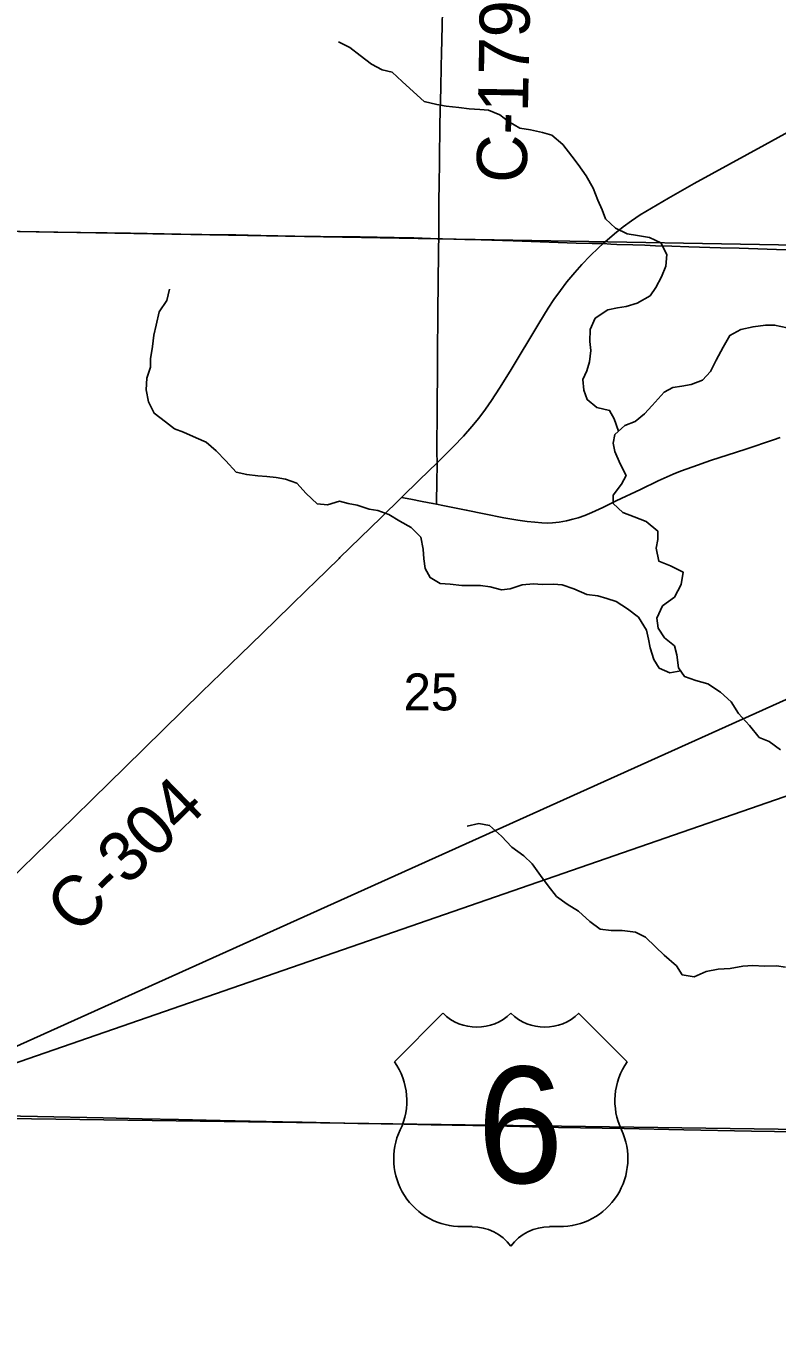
# Model space of a CAD drawing. Extents: x 0 to 34, y 0 to 22.
# Drawn here: x 4.764 to 5.615, y 15.338 to 16.807 of the extents above; entities that cross this region are included whole.
import ezdxf

# ---------------------------------------------------------------- set-up
doc = ezdxf.new("R2010")
doc.units = 0
for name, color, linetype in [('GM_X_Corporation', 7, 'Continuous'), ('GM_X_County_Road', 7, 'Continuous'), ('GM_X_County_Road_Text', 7, 'Continuous'), ('GM_X_Minor_River', 7, 'Continuous'), ('GM_X_Section_Text', 7, 'Continuous'), ('GM_X_State_Route', 7, 'Continuous'), ('GM_X_US_Location', 7, 'Continuous'), ('GM_X_US_Route', 7, 'Continuous'), ('GM_X_US_Shield', 7, 'Continuous'), ('SH_Data', 7, 'Continuous')]:
    doc.layers.add(name, color=color, linetype=linetype)

msp = doc.modelspace()

# ---------------------------------------------------------------- linework, layer by layer
at = {"layer": 'GM_X_Corporation'}
for points in [[(4.7439, 17.5807), (5.7581, 17.5537), (5.7459, 16.557), (4.7141, 16.575)], [(4.7141, 16.575), (5.7459, 16.557), (5.726, 15.5556), (4.7157, 15.5696)], [(4.7157, 15.5696), (5.726, 15.5556), (5.7061, 14.5519), (4.7065, 14.5692)]]:
    msp.add_lwpolyline(points, close=True, dxfattribs=at)
at = {"layer": 'GM_X_County_Road'}
for points in [[(5.232, 16.5662), (5.2321, 16.5737), (5.2321, 16.587), (5.2321, 16.5976), (5.2323, 16.6106), (5.2325, 16.6269), (5.2328, 16.6542), (5.2333, 16.6964), (5.2343, 16.7368), (5.2347, 16.7616), (5.235, 16.7759), (5.2358, 16.8076), (5.2368, 16.8424), (5.2374, 16.8642), (5.2384, 16.8921), (5.2387, 16.9089), (5.2399, 16.9455), (5.2405, 16.9723), (5.2412, 16.9928), (5.2416, 17.0058), (5.242, 17.0181), (5.2425, 17.0353), (5.2434, 17.0647)], [(5.4185, 16.5607), (5.4228, 16.5647), (5.4314, 16.5719), (5.4411, 16.5796), (5.4506, 16.5865), (5.4604, 16.5931), (5.473, 16.601), (5.4923, 16.6122), (5.5216, 16.6286), (5.6017, 16.6726), (5.6436, 16.6958), (5.6963, 16.725), (5.7198, 16.738), (5.7398, 16.7492), (5.7497, 16.7549)], [(4.6889, 16.5753), (4.6917, 16.5753), (4.7557, 16.5744), (4.7957, 16.5737), (4.8564, 16.5728), (4.8826, 16.5725), (4.9397, 16.5714), (4.9634, 16.5711), (5.0019, 16.5705), (5.0305, 16.5699), (5.069, 16.5692), (5.0982, 16.5688), (5.143, 16.5682), (5.1815, 16.5676), (5.2039, 16.5671), (5.232, 16.5662)], [(5.2301, 16.3123), (5.23, 16.3242), (5.23, 16.3422), (5.2301, 16.3571), (5.2303, 16.377), (5.2303, 16.3876), (5.2305, 16.4062), (5.2305, 16.4143), (5.2306, 16.4277), (5.2308, 16.4491), (5.2309, 16.4677), (5.231, 16.4851), (5.2312, 16.515), (5.2314, 16.5261), (5.2316, 16.5417), (5.2319, 16.5567), (5.232, 16.5662)], [(5.232, 16.5662), (5.2362, 16.5662), (5.2616, 16.5654), (5.2803, 16.5649), (5.3163, 16.5638), (5.3878, 16.5613), (5.406, 16.5607), (5.4129, 16.5606), (5.4185, 16.5607)], [(5.2301, 16.3123), (5.2316, 16.3138), (5.2488, 16.3309), (5.26, 16.3426), (5.2695, 16.3534), (5.2774, 16.363), (5.2849, 16.373), (5.2917, 16.3827), (5.3009, 16.3968), (5.313, 16.4163), (5.3453, 16.4702), (5.3561, 16.4876), (5.3626, 16.4974), (5.3699, 16.5075), (5.3774, 16.5173), (5.3861, 16.5278), (5.3944, 16.5371), (5.4038, 16.5469), (5.4132, 16.556), (5.4185, 16.5607)], [(5.4185, 16.5607), (5.4269, 16.5601), (5.434, 16.5598), (5.4521, 16.5591), (5.4657, 16.5587), (5.4777, 16.5583), (5.4962, 16.5578), (5.5156, 16.557), (5.5514, 16.5558), (5.5725, 16.5553), (5.5937, 16.5547), (5.6148, 16.5541), (5.6496, 16.5532), (5.6682, 16.553), (5.6924, 16.5527), (5.7136, 16.5527), (5.7344, 16.5529), (5.7459, 16.5531), (5.7477, 16.5532), (5.7493, 16.5533)], [(5.6191, 16.3408), (5.6114, 16.3383), (5.5801, 16.3279), (5.5695, 16.3244), (5.54, 16.3147), (5.52, 16.3079), (5.506, 16.3027), (5.4979, 16.2994), (5.4809, 16.2917), (5.4607, 16.282), (5.4332, 16.269), (5.4181, 16.2617), (5.4057, 16.256), (5.3977, 16.2527), (5.3901, 16.25), (5.3842, 16.2483), (5.377, 16.2466), (5.3685, 16.2452), (5.3611, 16.2443), (5.3556, 16.244), (5.3489, 16.2443), (5.3409, 16.2449), (5.3322, 16.2457), (5.3218, 16.2472), (5.3059, 16.25), (5.2834, 16.2545), (5.2633, 16.2587), (5.2365, 16.264), (5.2295, 16.2654)], [(5.1899, 16.273), (5.2104, 16.2928), (5.2301, 16.3123)], [(5.2295, 16.2654), (5.2296, 16.2694), (5.2298, 16.2887), (5.2301, 16.3123)], [(4.7186, 15.8132), (4.7288, 15.8231), (4.7596, 15.853), (4.8183, 15.9103), (4.84, 15.9317), (4.8761, 15.9669), (4.9636, 16.0526), (5.0072, 16.0951), (5.0319, 16.1188), (5.0648, 16.1509), (5.0824, 16.1685), (5.0919, 16.1775), (5.119, 16.204), (5.1199, 16.2049), (5.1663, 16.2499), (5.1899, 16.273)], [(5.2295, 16.2654), (5.2255, 16.2662), (5.2133, 16.2685), (5.2005, 16.271), (5.1899, 16.273)]]:
    msp.add_lwpolyline(points, dxfattribs=at)
at = {"layer": 'GM_X_Minor_River'}
for points in [[(5.4359, 16.3482), (5.4308, 16.3622), (5.4257, 16.3717), (5.4114, 16.375), (5.4002, 16.384), (5.3966, 16.3947), (5.3953, 16.4065), (5.4, 16.4166), (5.4029, 16.4268), (5.4043, 16.4397), (5.4033, 16.4499), (5.4036, 16.4632), (5.4095, 16.476), (5.4237, 16.4856), (5.4348, 16.4877), (5.4443, 16.4894), (5.4569, 16.4933), (5.4715, 16.5014), (5.4781, 16.5111), (5.4844, 16.5231), (5.4895, 16.5352), (5.4906, 16.5484), (5.4836, 16.5615), (5.4708, 16.5674), (5.4572, 16.5699), (5.4455, 16.5717), (5.4324, 16.578), (5.4212, 16.5889), (5.4172, 16.5988), (5.4125, 16.6099), (5.4071, 16.6233), (5.399, 16.6375), (5.3901, 16.6502), (5.3827, 16.6598), (5.3728, 16.6729), (5.3601, 16.6834), (5.3495, 16.6866), (5.3359, 16.6895), (5.3238, 16.6913), (5.3111, 16.6991), (5.3014, 16.7065), (5.2886, 16.7117), (5.2787, 16.7126), (5.2666, 16.7133), (5.2549, 16.715), (5.2405, 16.7164), (5.2299, 16.7181), (5.2156, 16.7218), (5.2033, 16.7327), (5.1906, 16.7443), (5.1794, 16.7548), (5.1681, 16.7577), (5.1557, 16.764), (5.143, 16.7737), (5.1314, 16.7827), (5.1183, 16.7894)], [(5.5063, 16.0764), (5.4939, 16.0741), (5.4819, 16.0797), (5.476, 16.0893), (5.4717, 16.1026), (5.4696, 16.1125), (5.4676, 16.1228), (5.4584, 16.1374), (5.446, 16.1468), (5.4333, 16.1553), (5.4224, 16.1586), (5.4122, 16.1614), (5.3997, 16.1632), (5.385, 16.1696), (5.3718, 16.174), (5.362, 16.1749), (5.3491, 16.1744), (5.3393, 16.175), (5.3267, 16.1741), (5.313, 16.1694), (5.3031, 16.1685), (5.2903, 16.1718), (5.2793, 16.1731), (5.2687, 16.1733), (5.2581, 16.1731), (5.2448, 16.1749), (5.2338, 16.1755), (5.2222, 16.1822), (5.2167, 16.1925), (5.2151, 16.2036), (5.2145, 16.2146), (5.2117, 16.2279), (5.2006, 16.2391), (5.1878, 16.2462), (5.1754, 16.2537), (5.163, 16.2584), (5.1532, 16.2598), (5.1396, 16.2642), (5.1294, 16.2663), (5.1196, 16.2688), (5.1059, 16.2645), (5.0942, 16.2658), (5.0819, 16.2775), (5.0711, 16.2891), (5.0583, 16.2939), (5.0477, 16.2956), (5.0371, 16.2969), (5.0269, 16.2975), (5.0144, 16.2989), (5.0023, 16.3018), (4.9908, 16.3145), (4.9796, 16.3257), (4.9685, 16.3358), (4.9572, 16.3406), (4.9429, 16.3469), (4.9324, 16.3509), (4.9223, 16.3587), (4.9096, 16.3684), (4.903, 16.3815), (4.9006, 16.3948), (4.9012, 16.408), (4.9053, 16.4205), (4.9054, 16.43), (4.9076, 16.444), (4.909, 16.4568), (4.9119, 16.4682), (4.9152, 16.4833), (4.9238, 16.496), (4.9267, 16.5089)], [(5.4947, 16.1955), (5.4816, 16.2007), (5.4784, 16.2155), (5.4805, 16.2254), (5.4803, 16.2349), (5.4673, 16.2457), (5.4537, 16.2509), (5.4406, 16.2561), (5.4297, 16.2662), (5.4299, 16.2757), (5.4393, 16.288), (5.4444, 16.2978), (5.4378, 16.3112), (5.4316, 16.325), (5.4299, 16.3345), (5.4316, 16.3443), (5.4428, 16.3547), (5.4547, 16.359), (5.4651, 16.3676), (5.474, 16.3773), (5.4875, 16.3922), (5.4975, 16.3977), (5.5074, 16.399), (5.5181, 16.4011), (5.531, 16.4061), (5.54, 16.4158), (5.5463, 16.4286), (5.5545, 16.4432), (5.562, 16.4567), (5.5746, 16.4633), (5.5883, 16.4665), (5.6024, 16.4681), (5.6126, 16.4683), (5.627, 16.4653)], [(5.6193, 15.9871), (5.6066, 15.9965), (5.5953, 16.0012), (5.5842, 16.0147), (5.5719, 16.0282), (5.5634, 16.0413), (5.5515, 16.0525), (5.5369, 16.0619), (5.5233, 16.0656), (5.5105, 16.07), (5.5039, 16.08), (5.5019, 16.0945), (5.4991, 16.1048), (5.4879, 16.1141), (5.4809, 16.1248), (5.4792, 16.1362), (5.4855, 16.1502), (5.4994, 16.1601), (5.5068, 16.1744), (5.509, 16.1884), (5.4947, 16.1955)], [(5.6251, 15.7408), (5.6149, 15.7422), (5.6013, 15.742), (5.588, 15.7427), (5.5766, 15.7418), (5.5625, 15.7394), (5.5489, 15.7385), (5.5352, 15.7357), (5.5214, 15.7299), (5.5078, 15.7321), (5.5015, 15.7421), (5.4874, 15.7545), (5.4777, 15.7638), (5.4665, 15.7746), (5.4549, 15.7805), (5.4401, 15.7823), (5.4276, 15.7822), (5.4151, 15.784), (5.4032, 15.7925), (5.3905, 15.8042), (5.3777, 15.812), (5.3654, 15.821), (5.3562, 15.8329), (5.3473, 15.8448), (5.3381, 15.8579), (5.3284, 15.8668), (5.3149, 15.8766), (5.303, 15.8893), (5.2896, 15.9013), (5.2775, 15.9034), (5.2642, 15.9007)]]:
    msp.add_lwpolyline(points, dxfattribs=at)
at = {"layer": 'GM_X_State_Route'}
msp.add_lwpolyline([(4.7189, 15.5728), (4.758, 15.572), (4.7772, 15.5716), (4.8518, 15.57), (4.896, 15.5691), (4.937, 15.5682), (4.9842, 15.5672), (5.0184, 15.5664), (5.0551, 15.5656), (5.0774, 15.565), (5.1402, 15.5637), (5.193, 15.5627), (5.2235, 15.562), (5.2944, 15.5608), (5.3677, 15.5592), (5.4423, 15.558), (5.51, 15.5566), (5.5865, 15.555), (5.6126, 15.5546), (5.6747, 15.5533), (5.7046, 15.5527), (5.729, 15.5524)], dxfattribs=at)
at = {"layer": 'GM_X_US_Route'}
msp.add_lwpolyline([(4.7189, 15.5728), (4.758, 15.572), (4.7772, 15.5716), (4.8518, 15.57), (4.896, 15.5691), (4.937, 15.5682), (4.9842, 15.5672), (5.0184, 15.5664), (5.0551, 15.5656), (5.0774, 15.565), (5.1402, 15.5637), (5.193, 15.5627), (5.2235, 15.562), (5.2944, 15.5608), (5.3677, 15.5592), (5.4423, 15.558), (5.51, 15.5566), (5.5865, 15.555), (5.6126, 15.5546), (5.6747, 15.5533), (5.7046, 15.5527), (5.729, 15.5524)], dxfattribs=at)
at = {"layer": 'GM_X_US_Shield'}
for p, q in [((5.2368, 15.6885), (5.1819, 15.6335)), ((5.4456, 15.6335), (5.3906, 15.6885)), ((5.2588, 15.4468), (5.2698, 15.4468)), ((5.3577, 15.4468), (5.3687, 15.4468))]:
    msp.add_line(p, q, dxfattribs=at)
for centre, radius, start, end in [((5.2753, 15.7277), 0.0549, 225.573, 314.427), ((5.3522, 15.7277), 0.0549, 225.573, 314.427), ((5.1189, 15.5894), 0.0769, 334.5471, 35.0009), ((5.5086, 15.5894), 0.0769, 144.9991, 205.4529), ((5.2579, 15.5237), 0.0769, 154.8319, 270.6383), ((5.3695, 15.5237), 0.0769, 269.3617, 25.1681), ((5.2698, 15.3918), 0.0549, 36.8699, 90), ((5.3577, 15.3918), 0.0549, 90, 143.1301)]:
    msp.add_arc(centre, radius, start, end, dxfattribs=at)
at = {"layer": 'SH_Data'}
msp.add_lwpolyline([(4.574, 15.5703), (9.2813, 17.2011), (9.2813, 17.6911)], close=True, dxfattribs=at)

# ---------------------------------------------------------------- texts
at = {"layer": 'GM_X_County_Road_Text'}
for s, rotation, p in [('C-179', 88.9096, (5.3316, 16.629)), ('C-304', 44.228, (4.8217, 15.7759))]:
    msp.add_text(s, height=0.05682, rotation=rotation, dxfattribs=at).set_placement(p)
at = {"layer": 'GM_X_Section_Text'}
msp.add_text('25', height=0.04186, rotation=0, dxfattribs=at).set_placement((5.1921, 16.0317))
at = {"layer": 'GM_X_US_Location'}
for s in ['0', '/']:
    msp.add_text(s, height=0.000189, dxfattribs=at).set_placement((5.3137, 15.5611))
msp.add_text('6', height=0.000189, rotation=0, dxfattribs=at).set_placement((5.2946, 15.5219))
at = {"layer": 'GM_X_US_Shield'}
msp.add_text('6', height=0.1318, dxfattribs=at).set_placement((5.2754, 15.4962))

doc.saveas('drawing.dxf')
